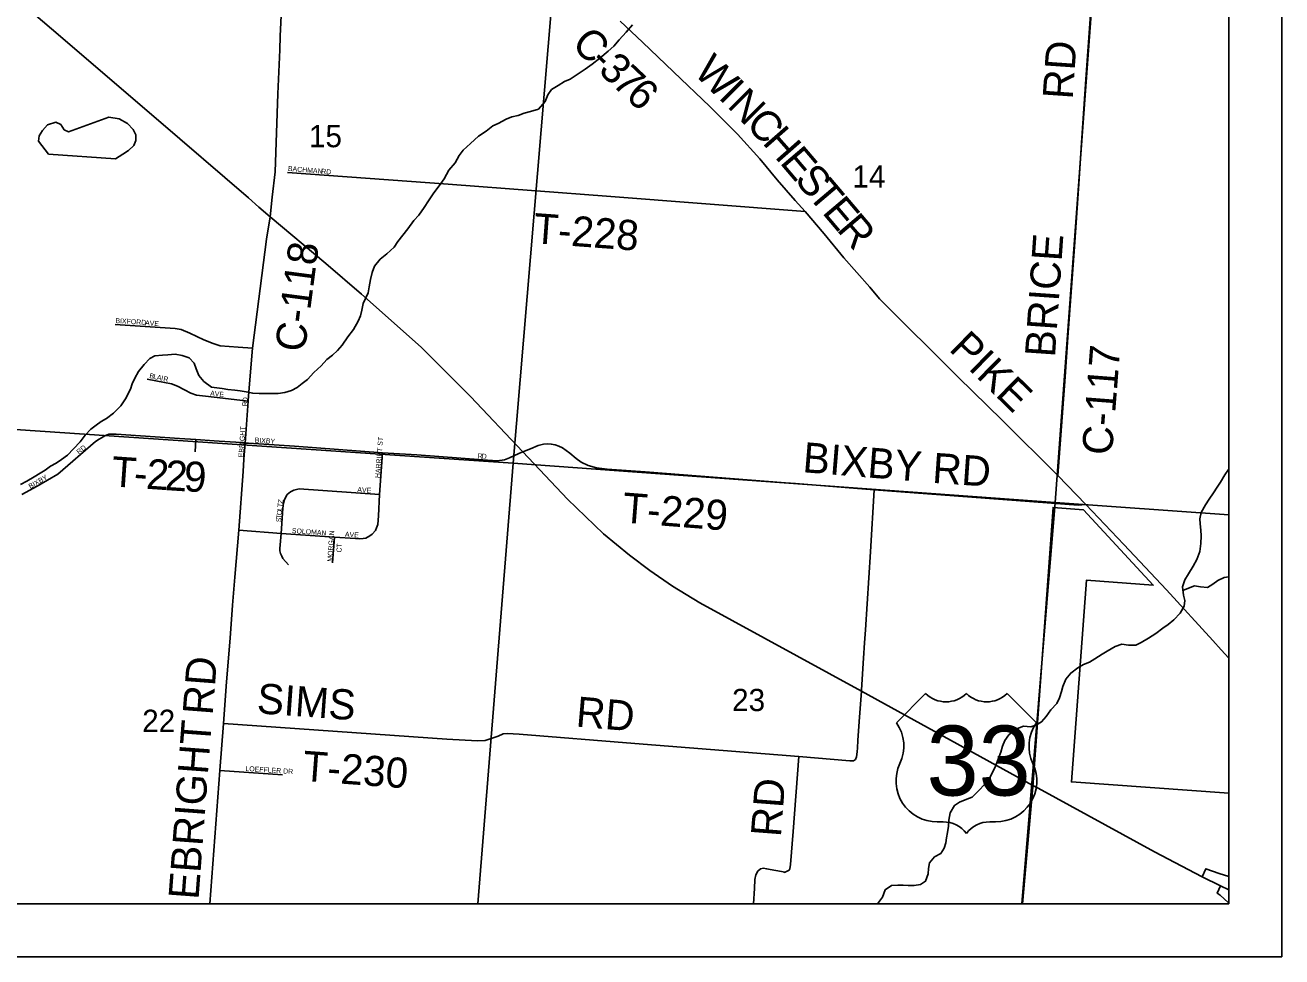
# Model space of a CAD drawing. Extents: x 0 to 34, y 0 to 22.
# Drawn here: x 7.131 to 9.5, y 14 to 15.756 of the extents above; entities that cross this region are included whole.
import ezdxf

# ---------------------------------------------------------------- set-up
doc = ezdxf.new("R2010")
doc.units = 0
for name, color, linetype in [('GM_X_City_Street', 7, 'Continuous'), ('GM_X_City_Street_Text', 7, 'Continuous'), ('GM_X_Corporation', 7, 'Continuous'), ('GM_X_County_Road', 7, 'Continuous'), ('GM_X_County_Road_Text', 7, 'Continuous'), ('GM_X_Interchange_Ramps', 7, 'Continuous'), ('GM_X_Minor_Lake', 7, 'Continuous'), ('GM_X_Minor_River', 7, 'Continuous'), ('GM_X_Section', 7, 'Continuous'), ('GM_X_Section_Text', 7, 'Continuous'), ('GM_X_Township', 7, 'Continuous'), ('GM_X_Township_Road', 7, 'Continuous'), ('GM_X_Township_Road_Text', 7, 'Continuous'), ('GM_X_Township_Subdivision', 7, 'Continuous'), ('GM_X_Township_Subdivision_Text', 7, 'Continuous'), ('GM_X_US_Location', 7, 'Continuous'), ('GM_X_US_Route', 7, 'Continuous'), ('GM_X_US_Shield', 7, 'Continuous'), ('SH_Data', 7, 'Continuous')]:
    doc.layers.add(name, color=color, linetype=linetype)

msp = doc.modelspace()

# ---------------------------------------------------------------- linework, layer by layer
at = {"layer": 'GM_X_City_Street'}
for points in [[(7.6113, 15.7091), (7.6124, 15.7349), (7.6188, 15.8768), (7.6274, 15.9846), (7.6347, 16.1465), (7.637, 16.1746)], [(7.5973, 15.4317), (7.6024, 15.4796), (7.608, 15.6266), (7.6113, 15.7091)], [(7.6257, 15.478), (7.9288, 15.4559), (8.0937, 15.4438)], [(7.5439, 14.9382), (7.5462, 14.9684), (7.5518, 15.0471), (7.5527, 15.0575)], [(7.1255, 14.8711), (7.154, 14.887), (7.1931, 14.9094), (7.2643, 14.9712), (7.2708, 14.9757), (7.2754, 14.9782), (7.2819, 14.9817), (7.2893, 14.9851), (7.2981, 14.9851)], [(7.4972, 14.9718), (7.5283, 14.9698), (7.5462, 14.9684), (7.5526, 14.9682), (7.6392, 14.9622), (7.8053, 14.9501), (7.8694, 14.9459), (7.9942, 14.9367), (8.0208, 14.9351), (8.035, 14.9369), (8.0444, 14.9402), (8.0618, 14.9485), (8.0619, 14.9485)], [(9.3857, 14.5788), (9.4, 14.563)]]:
    msp.add_lwpolyline(points, dxfattribs=at)
at = {"layer": 'GM_X_Corporation'}
for points in [[(9.4, 14.3088), (9.1035, 14.3296), (9.1316, 14.7099), (9.2577, 14.7007), (9.1802, 14.7843), (9.1261, 14.8422), (9.0689, 14.847), (9.0306, 14.3207), (9.0109, 14.1)], [(9.0109, 14.1), (9.4, 14.1), (9.4, 14.3088)]]:
    msp.add_lwpolyline(points, dxfattribs=at)
at = {"layer": 'GM_X_County_Road'}
for points in [[(9.0778, 14.9072), (9.0915, 15.093), (9.0967, 15.1679), (9.1089, 15.338), (9.1173, 15.457), (9.1225, 15.5343), (9.1314, 15.6627), (9.1428, 15.8288), (9.1459, 15.8726)], [(8.2531, 15.7636), (8.2953, 15.7237), (8.3535, 15.6679), (8.4217, 15.6023), (8.4739, 15.5504), (8.5159, 15.5041), (8.5491, 15.4646), (8.583, 15.4256), (8.6013, 15.4047), (8.6371, 15.3624), (8.6745, 15.3175), (8.7236, 15.262), (8.7415, 15.2402), (8.8899, 15.0925), (8.973, 15.0117), (9.0778, 14.9072), (9.1304, 14.8527), (9.202, 14.7773), (9.2824, 14.692), (9.3701, 14.5962), (9.3857, 14.5788)], [(7.5688, 15.2153), (7.5864, 15.3526), (7.5933, 15.3949), (7.5973, 15.4317)], [(7.5527, 15.0575), (7.56, 15.147), (7.5688, 15.2153)], [(7.4797, 14.1), (7.4985, 14.3509), (7.5055, 14.4401), (7.5111, 14.5185), (7.5176, 14.6009), (7.5225, 14.663), (7.5268, 14.7153), (7.534, 14.804), (7.5422, 14.9145), (7.5439, 14.9382)]]:
    msp.add_lwpolyline(points, dxfattribs=at)
at = {"layer": 'GM_X_Interchange_Ramps'}
for points in [[(9.4, 14.1515), (9.3816, 14.1572), (9.3569, 14.1662), (9.3499, 14.1506)], [(9.3844, 14.1336), (9.3783, 14.12), (9.3835, 14.1161), (9.3914, 14.1096), (9.399, 14.1027), (9.4, 14.1017)]]:
    msp.add_lwpolyline(points, dxfattribs=at)
at = {"layer": 'GM_X_Minor_Lake'}
for points in [[(7.3019, 15.504), (7.3159, 15.5126), (7.3266, 15.5197), (7.3361, 15.5288), (7.3399, 15.5383), (7.34, 15.5493), (7.3351, 15.5592), (7.3246, 15.5706), (7.3084, 15.579), (7.2895, 15.5822), (7.213, 15.5546), (7.2051, 15.5588), (7.1987, 15.5687), (7.1896, 15.5733), (7.1737, 15.5677), (7.1642, 15.5572), (7.1581, 15.5473), (7.1565, 15.5375), (7.1756, 15.5127)], [(7.1756, 15.5127), (7.3019, 15.504)]]:
    msp.add_lwpolyline(points, dxfattribs=at)
at = {"layer": 'GM_X_Minor_River'}
for points in [[(8.2764, 15.7564), (8.2642, 15.7425), (8.2513, 15.7281), (8.241, 15.7161), (8.23, 15.707), (8.2148, 15.6934), (8.2003, 15.6825), (8.1867, 15.6731), (8.1719, 15.6626), (8.1586, 15.6543), (8.1483, 15.6495), (8.1362, 15.6423), (8.1237, 15.6348), (8.1164, 15.6246), (8.1114, 15.6117), (8.0988, 15.5974), (8.0841, 15.5929), (8.072, 15.59), (8.0606, 15.5859), (8.0485, 15.5829), (8.0379, 15.5784), (8.0227, 15.5705), (8.0132, 15.566), (8.0003, 15.5562), (7.9862, 15.5465), (7.971, 15.5329), (7.9573, 15.5205), (7.9493, 15.5099), (7.9417, 15.4966), (7.9299, 15.4823), (7.9214, 15.466), (7.9115, 15.4528), (7.902, 15.44), (7.8917, 15.4249), (7.8837, 15.4124), (7.8734, 15.3976), (7.8639, 15.3875), (7.8528, 15.3723), (7.8433, 15.3603), (7.8341, 15.3482), (7.8269, 15.3376), (7.8132, 15.3252), (7.8003, 15.3146), (7.79, 15.3018), (7.7854, 15.29), (7.7823, 15.2768), (7.7799, 15.2624), (7.7779, 15.2517)], [(7.1227, 14.8903), (7.1348, 14.8963), (7.1485, 14.9046), (7.1598, 14.9114), (7.1693, 14.9171), (7.1795, 14.9247), (7.1902, 14.9303), (7.2, 14.9372), (7.2114, 14.9455), (7.2228, 14.9572), (7.2349, 14.9704), (7.2448, 14.9833), (7.2554, 14.9943), (7.2653, 15.0022), (7.2747, 15.0087), (7.285, 15.0143), (7.2982, 15.0245), (7.3119, 15.0385), (7.3206, 15.0514), (7.3301, 15.07), (7.3332, 15.0798), (7.3381, 15.0904), (7.345, 15.1029), (7.3556, 15.1166), (7.3662, 15.1275), (7.3761, 15.1324), (7.3901, 15.1339), (7.4007, 15.1343), (7.4143, 15.1358), (7.4276, 15.1331), (7.4404, 15.1289), (7.4502, 15.1187), (7.4536, 15.108), (7.4589, 15.0959), (7.4683, 15.0845), (7.483, 15.0739), (7.4929, 15.0723), (7.5031, 15.0708), (7.5137, 15.0693), (7.5265, 15.0677), (7.5367, 15.0666), (7.5481, 15.0646), (7.5606, 15.0623), (7.5727, 15.0619), (7.5852, 15.0619), (7.5954, 15.0615), (7.6083, 15.0619), (7.6211, 15.0634), (7.6336, 15.0675), (7.6442, 15.0732), (7.6537, 15.0804), (7.6639, 15.0883), (7.6757, 15.1012), (7.6894, 15.1137), (7.7, 15.1258), (7.711, 15.1337), (7.7205, 15.1428), (7.7288, 15.1526), (7.7395, 15.1682), (7.7501, 15.1825), (7.7592, 15.1977), (7.7638, 15.2079), (7.7661, 15.2185), (7.7684, 15.2314)], [(7.7779, 15.2517), (7.7684, 15.2314)], [(9.1372, 14.5552), (9.1475, 14.5616), (9.1611, 14.5707), (9.171, 14.576), (9.1857, 14.585), (9.1986, 14.5892), (9.2111, 14.5873), (9.2247, 14.5876), (9.2349, 14.5922), (9.2486, 14.6005), (9.2622, 14.6095), (9.2759, 14.6194), (9.2857, 14.6266), (9.2964, 14.6349), (9.3085, 14.6477), (9.3161, 14.661), (9.3169, 14.6716), (9.3143, 14.6818), (9.3128, 14.6974), (9.3174, 14.7103), (9.3238, 14.7216), (9.3329, 14.736), (9.3398, 14.7489), (9.3451, 14.7637), (9.3474, 14.7788), (9.3482, 14.7936), (9.3475, 14.8042), (9.346, 14.816), (9.3457, 14.8258), (9.348, 14.8376), (9.3563, 14.852), (9.3632, 14.8626), (9.3711, 14.8747), (9.378, 14.8849), (9.3841, 14.8948), (9.3924, 14.9084), (9.3993, 14.9182), (9.4, 14.9199)], [(9.3134, 14.6906), (9.3211, 14.6936), (9.3351, 14.6992), (9.3468, 14.6973), (9.3601, 14.6958), (9.3699, 14.7026), (9.3794, 14.709), (9.3915, 14.7147), (9.4, 14.716)], [(8.738, 14.1), (8.7471, 14.1127), (8.7524, 14.1264), (8.7645, 14.1343), (8.7763, 14.1351), (8.7861, 14.135), (8.796, 14.1343), (8.8073, 14.1346), (8.8187, 14.1361), (8.8281, 14.1425), (8.8331, 14.1562), (8.8343, 14.1664), (8.8358, 14.177), (8.8453, 14.1884), (8.8574, 14.1948), (8.8635, 14.2047), (8.8665, 14.2149), (8.8681, 14.2244), (8.87, 14.2346), (8.8715, 14.2463), (8.8723, 14.2573), (8.8746, 14.2717), (8.883, 14.2854), (8.8925, 14.2914), (8.9061, 14.2975), (8.9163, 14.3008), (8.9285, 14.313), (8.9402, 14.3254), (8.9482, 14.3353), (8.9539, 14.3459), (8.9608, 14.3607), (8.9657, 14.3743), (8.9703, 14.3857), (8.9737, 14.397), (8.9779, 14.4076), (8.9855, 14.4182), (8.9984, 14.4288), (9.0128, 14.4345), (9.0268, 14.4337), (9.0378, 14.4375), (9.0473, 14.4428), (9.0556, 14.453), (9.0643, 14.4655), (9.0761, 14.4772), (9.081, 14.4882), (9.0845, 14.4999), (9.0875, 14.5094), (9.0929, 14.5234), (9.102, 14.5348), (9.1156, 14.545), (9.1262, 14.5507), (9.1372, 14.5552)]]:
    msp.add_lwpolyline(points, dxfattribs=at)
at = {"layer": 'GM_X_Section'}
for p, q in [((9.4, 14.8328), (9.4, 15.8522)), ((6.9683, 14.1), (7.9848, 14.1)), ((7.9848, 14.1), (9.0101, 14.1))]:
    msp.add_line(p, q, dxfattribs=at)
for points in [[(7.1133, 16.022), (8.1366, 15.948), (8.0511, 14.9304), (7.0289, 14.9993)], [(8.1366, 15.948), (9.1474, 15.8714), (9.0729, 14.8565), (8.0511, 14.9304)]]:
    msp.add_lwpolyline(points, close=True, dxfattribs=at)
for points in [[(9.4, 15.8522), (9.1474, 15.8714), (9.0729, 14.8565), (9.4, 14.8328)], [(7.9848, 14.1), (8.0511, 14.9304), (7.0289, 14.9993), (6.9683, 14.1)], [(9.0101, 14.1), (9.0729, 14.8565), (8.0511, 14.9304), (7.9848, 14.1)], [(9.4, 14.8328), (9.0729, 14.8565), (9.0101, 14.1)], [(9.0101, 14.1), (9.4, 14.1), (9.4, 14.8328)]]:
    msp.add_lwpolyline(points, dxfattribs=at)
at = {"layer": 'GM_X_Township'}
msp.add_lwpolyline([(3.9541, 14.1), (9.4, 14.1), (9.4, 17.8295)], dxfattribs=at)
at = {"layer": 'GM_X_Township_Road'}
for points in [[(8.0937, 15.4438), (8.0948, 15.4437), (8.2273, 15.4336), (8.6013, 15.4047)], [(7.2981, 14.9851), (7.3029, 14.9851), (7.4226, 14.9771), (7.4535, 14.9748), (7.4875, 14.9724), (7.4972, 14.9718)], [(8.0619, 14.9485), (8.0697, 14.952), (8.0837, 14.9575), (8.0984, 14.9634), (8.1083, 14.9662), (8.116, 14.9668), (8.123, 14.9665), (8.1305, 14.9652), (8.1372, 14.9627), (8.144, 14.9594), (8.1578, 14.9492), (8.1698, 14.9389), (8.1794, 14.9325), (8.1925, 14.926), (8.2085, 14.9213), (8.2286, 14.9191), (8.3003, 14.9139), (8.5646, 14.8935), (8.5834, 14.892)], [(8.5834, 14.892), (8.7316, 14.8803), (8.8573, 14.8705), (9.1158, 14.8511), (9.1304, 14.8527)], [(8.7113, 14.5626), (8.7131, 14.5916), (8.715, 14.6162), (8.7247, 14.7633), (8.7316, 14.8803)], [(8.7078, 14.503), (8.7113, 14.5626)], [(8.7036, 14.4434), (8.7076, 14.5007), (8.7078, 14.503)], [(7.5055, 14.4401), (7.9262, 14.4104), (7.9838, 14.4072), (7.9985, 14.408), (8.0233, 14.4157), (8.0326, 14.4203), (8.0398, 14.4211), (8.0624, 14.4199), (8.2807, 14.4022), (8.5894, 14.3776)], [(8.7, 14.3938), (8.701, 14.4079), (8.7036, 14.4434)], [(8.569, 14.1619), (8.5713, 14.1633), (8.5727, 14.166), (8.5742, 14.1741), (8.5787, 14.2364), (8.5894, 14.3776), (8.686, 14.3692), (8.6924, 14.3697), (8.6963, 14.3722), (8.6985, 14.3772), (8.6995, 14.3863), (8.7, 14.3938)], [(8.5043, 14.1), (8.5062, 14.1291), (8.507, 14.146), (8.5083, 14.1549), (8.5121, 14.1617), (8.5176, 14.1656), (8.5228, 14.1669), (8.529, 14.166), (8.564, 14.1597), (8.5617, 14.1593), (8.5679, 14.1612), (8.569, 14.1619)]]:
    msp.add_lwpolyline(points, dxfattribs=at)
at = {"layer": 'GM_X_Township_Subdivision'}
for points in [[(7.3009, 15.1916), (7.4141, 15.184), (7.4253, 15.1826), (7.4416, 15.1751), (7.4685, 15.1627), (7.4858, 15.1558), (7.4989, 15.1518), (7.5331, 15.1488), (7.56, 15.147)], [(7.3612, 15.0884), (7.3944, 15.0827), (7.4072, 15.0796), (7.4188, 15.0753), (7.4319, 15.0688), (7.4436, 15.0622), (7.4546, 15.0583), (7.4711, 15.0566), (7.5039, 15.0528), (7.5518, 15.0471)], [(7.4517, 14.9519), (7.4535, 14.9748)], [(7.7733, 14.7888), (7.7809, 14.7933), (7.7854, 14.7967), (7.7916, 14.8033), (7.7939, 14.8086), (7.7963, 14.8148), (7.7976, 14.8312), (7.7991, 14.8715), (7.8053, 14.9501)], [(7.6138, 14.7979), (7.6174, 14.8457), (7.6185, 14.855), (7.6204, 14.8622), (7.6254, 14.8712), (7.6317, 14.8764), (7.6382, 14.8797), (7.6481, 14.8822), (7.7991, 14.8715)], [(7.534, 14.804), (7.6138, 14.7979), (7.7143, 14.7909), (7.7541, 14.7886), (7.7624, 14.788), (7.7688, 14.7884), (7.7733, 14.7888)], [(7.6281, 14.7386), (7.6173, 14.7509), (7.615, 14.7549), (7.6129, 14.7601), (7.6118, 14.7651), (7.6116, 14.7696), (7.612, 14.7763), (7.6138, 14.7979)], [(7.7109, 14.7425), (7.7143, 14.7909)], [(7.4985, 14.3509), (7.6167, 14.343)]]:
    msp.add_lwpolyline(points, dxfattribs=at)
at = {"layer": 'GM_X_US_Route'}
for points in [[(7.0829, 15.8326), (7.181, 15.7488), (7.3784, 15.5801), (7.5526, 15.4305), (7.5722, 15.4128), (7.5933, 15.3949), (7.6981, 15.3069), (7.7657, 15.249), (7.878, 15.1492), (7.927, 15.1002), (7.9709, 15.0563), (8.0697, 14.952), (8.1538, 14.8626), (8.2216, 14.7971), (8.2705, 14.7571), (8.3091, 14.728), (8.3517, 14.6986), (8.4028, 14.6674), (8.7076, 14.5007), (9.0309, 14.3231), (9.0406, 14.3177)], [(9.0406, 14.3177), (9.2597, 14.198), (9.3499, 14.1506), (9.3844, 14.1336), (9.4, 14.1264)]]:
    msp.add_lwpolyline(points, dxfattribs=at)
at = {"layer": 'GM_X_US_Shield'}
for p, q in [((8.8286, 14.4963), (8.7736, 14.4413)), ((9.0373, 14.4413), (8.9824, 14.4963)), ((8.8505, 14.2546), (8.8615, 14.2546)), ((8.9494, 14.2546), (8.9604, 14.2546))]:
    msp.add_line(p, q, dxfattribs=at)
for centre, radius, start, end in [((8.867, 14.5355), 0.0549, 225.573, 314.427), ((8.9439, 14.5355), 0.0549, 225.573, 314.427), ((8.7106, 14.3972), 0.0769, 334.5471, 35.0009), ((9.1003, 14.3972), 0.0769, 144.9991, 205.4529), ((8.8497, 14.3315), 0.0769, 154.8319, 270.6383), ((8.9613, 14.3315), 0.0769, 269.3617, 25.1681), ((8.8615, 14.1996), 0.0549, 36.8699, 90), ((8.9494, 14.1996), 0.0549, 90, 143.1301)]:
    msp.add_arc(centre, radius, start, end, dxfattribs=at)
at = {"layer": 'SH_Data'}
for p, q in [((9.5, 21), (9.5, 14)), ((9.4, 20.9), (9.4, 14.1)), ((2.6, 14.1), (9.4, 14.1)), ((2.5, 14), (9.5, 14))]:
    msp.add_line(p, q, dxfattribs=at)

# ---------------------------------------------------------------- texts
at = {"layer": 'GM_X_City_Street_Text'}
for s, rotation, p in [('BACHMAN', 355.1005, (7.6265, 15.4812)), ('RD', 353.9946, (7.689, 15.4762)), ('R', 89.0771, (7.5504, 15.0377)), ('D', 85.2727, (7.5505, 15.045)), ('EBRIGHT', 86.1845, (7.5429, 14.9412)), ('BIXBY', 356.0061, (7.5639, 14.9694)), ('RD', 38.6545, (7.2328, 14.9465)), ('R', 355.7708, (7.984, 14.9394)), ('D', 358.3299, (7.9919, 14.9388)), ('BIXBY', 30.0724, (7.1413, 14.8817))]:
    msp.add_text(s, height=0.00947, rotation=rotation, dxfattribs=at).set_placement(p)
at = {"layer": 'GM_X_County_Road_Text'}
for s, height, rotation, p in [('C', 0.0568, 316.3497, (8.1591, 15.7171)), ('W', 0.0568, 315.2387, (8.3896, 15.6653)), ('RD', 0.05682, 86.055, (9.1057, 15.6151)), ('-', 0.0568, 316.3495, (8.1929, 15.6848)), ('3', 0.0568, 316.3951, (8.2098, 15.6687)), ('7', 0.0568, 316.5392, (8.2352, 15.6445)), ('6', 0.0568, 316.9897, (8.261, 15.6201)), ('I', 0.0568, 315.2373, (8.4363, 15.6189)), ('N', 0.0568, 314.9176, (8.4528, 15.6025)), ('C', 0.0568, 313.2997, (8.4878, 15.5674)), ('H', 0.0568, 311.2857, (8.5195, 15.5339)), ('E', 0.0568, 310.3587, (8.5523, 15.4965)), ('S', 0.0568, 310.2977, (8.5798, 15.4641)), ('T', 0.0568, 310.3033, (8.6046, 15.4349)), ('E', 0.0568, 310.3037, (8.6321, 15.4025)), ('R', 0.0568, 310.3869, (8.6596, 15.37)), ('BRICE', 0.05682, 86.047, (9.0723, 15.129)), ('C-118', 0.05682, 82.5328, (7.6584, 15.1382)), ('PIKE', 0.05682, 315.6511, (8.8709, 15.1439)), ('C-117', 0.05682, 85.6016, (9.1797, 14.9443)), ('RD', 0.05682, 85.564, (7.4849, 14.4545)), ('EBRIGHT', 0.05682, 85.7344, (7.4582, 14.1069))]:
    msp.add_text(s, height=height, rotation=rotation, dxfattribs=at).set_placement(p)
at = {"layer": 'GM_X_Section_Text'}
for s, p in [('15', (7.6663, 15.5258)), ('14', (8.6905, 15.4498)), ('23', (8.4638, 14.4632)), ('22', (7.3521, 14.4239))]:
    msp.add_text(s, height=0.04186, rotation=0, dxfattribs=at).set_placement(p)
at = {"layer": 'GM_X_Township_Road_Text'}
for s, height, rotation, p in [('T-228', 0.05682, 355.7956, (8.088, 15.3452)), ('BIXBY', 0.05682, 355.3645, (8.5956, 14.9135)), ('RD', 0.05682, 356.0924, (8.8401, 14.8934)), ('T', 0.0568, 355.9809, (7.2927, 14.8869)), ('2', 0.0568, 356.0432, (7.3585, 14.8823)), ('2', 0.0568, 356.2796, (7.3936, 14.8798)), ('9', 0.0568, 357.2875, (7.4297, 14.8775)), ('-', 0.0568, 356.0061, (7.3352, 14.8839)), ('T-229', 0.05682, 355.5134, (8.2557, 14.8187)), ('SIMS', 0.05682, 355.8724, (7.5671, 14.4592)), ('RD', 0.05682, 355.0717, (8.1682, 14.4342)), ('T-230', 0.05682, 355.7949, (7.6532, 14.3319)), ('RD', 0.05682, 85.5667, (8.5557, 14.2249))]:
    msp.add_text(s, height=height, rotation=rotation, dxfattribs=at).set_placement(p)
at = {"layer": 'GM_X_Township_Subdivision_Text'}
for s, rotation, p in [('BIXFORD', 356.2504, (7.3014, 15.1945)), ('AVE', 356.0494, (7.3573, 15.1904)), ('B', 347.5423, (7.365, 15.0911)), ('L', 347.5613, (7.3724, 15.0895)), ('A', 347.5542, (7.3789, 15.0881)), ('I', 347.5328, (7.387, 15.0863)), ('R', 348.809, (7.3913, 15.0853)), ('AVE', 354.0895, (7.4798, 15.0578)), ('HARRIET ST', 85.7106, (7.8004, 14.902)), ('AVE', 356.0569, (7.7573, 14.8762)), ('T', 84.5414, (7.6164, 14.8469)), ('Z', 79.5901, (7.617, 14.8534)), ('S', 84.5286, (7.6137, 14.8187)), ('T', 84.5014, (7.6143, 14.8254)), ('O', 84.5413, (7.615, 14.832)), ('L', 84.5014, (7.6158, 14.8403)), ('SOLOMAN', 355.8545, (7.6339, 14.7987)), ('MORGAN', 86.3071, (7.7104, 14.7445)), ('AVE', 356.0569, (7.7339, 14.792)), ('CT', 86.8222, (7.7275, 14.7619)), ('LOEFFLER DR', 356.2274, (7.5464, 14.3504))]:
    msp.add_text(s, height=0.00947, rotation=rotation, dxfattribs=at).set_placement(p)
at = {"layer": 'GM_X_US_Location'}
for s in ['0', '/']:
    msp.add_text(s, height=0.000189, dxfattribs=at).set_placement((8.9054, 14.3689))
msp.add_text('33', height=0.000189, rotation=0, dxfattribs=at).set_placement((8.8663, 14.3297))
at = {"layer": 'GM_X_US_Shield'}
msp.add_text('33', height=0.13184, dxfattribs=at).set_placement((8.8304, 14.304))

doc.saveas('drawing.dxf')
